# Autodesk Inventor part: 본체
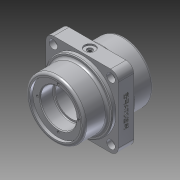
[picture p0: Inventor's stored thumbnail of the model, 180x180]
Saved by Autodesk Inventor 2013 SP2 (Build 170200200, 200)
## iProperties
Created: 2023-10
Part Number: 본체
Material: 알루미늄 6061
Document SubType Name: Modeling
Designer: i
Density: 2.71 g/cm^3
Mass: 1123.72 g
Surface Area: 610.083 cm^2
Volume: 414.656 cm^3
Author: i
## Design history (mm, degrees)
sketch "스케치1"
  geometry: L1 (-47, 47)-(47, 47); L2 (47, 47)-(47, -47); L3 (47, -47)-(-47, -47); L4 (-47, -47)-(-47, 47); L5 (-47, 47)-(47, -47); L6 (47, 47)-(-47, -47); 1 further point
  constraints: 12 end point, 2 midpoint, 2 parallel, 1 horizontal, 1 perpendicular
  dimensions: "d0" = 94 distance of L2.end L3.end; "d1" = 94 distance of L1.end L2.end
extrude "돌출1" new body sketch "스케치1" stored distance "d2" = 20; taper "d3" = 0 deg
sketch "스케치2"
  geometry: C1 r 44 at (0, 0); 1 further point
  constraints: 1 centre point, 1 coincident
  dimensions: "d4" = 88 diameter of C1
extrude "돌출2" join sketch "스케치2" distance "d6" = 5; taper "d7" = 0 deg
sketch "스케치3"
  geometry: C1 r 44 at (0, 0) reference; C2 r 38 at (0, 0)
  constraints: 1 centre point, 1 coincident
  dimensions: "d8" = 76 diameter of C2
extrude "돌출3" join sketch "스케치3" distance "d9" = 30; taper "d10" = 0 deg
sketch "스케치4"
  geometry: L1 (38, 45)-(-38, 45) reference; L2 (38, -45)-(-38, -45) reference; L3 (0, 45)-(0, -45); L4 (33, 45)-(33, 41); L5 (33, 41)-(23.5, 41); L6 (23.5, 41)-(23.5, 24); L7 (23.5, 24)-(20.5, 24); L8 (20.5, 24)-(20.5, -24); L9 (20.5, -24)-(23.5, -24); L10 (23.5, -24)-(23.5, -41); L11 (23.5, -41)-(33, -41); L12 (33, -41)-(33, -45); 1 further point
  constraints: 20 end point, 7 parallel, 3 collinear, 2 midpoint, 2 perpendicular, 2 point on line
  dimensions: "d11" = 66 diameter of L4 L3; "d13" = 4 distance of L4.start L4.end; "d14" = 47 diameter of L6 L3; "d15" = 17 distance of L5.end L6.end; "d16" = 17 distance of L9.end L10.end; "d17" = 41 diameter of L8 L3
revolve "회전1" sketch "스케치4" stored, may be unused: angle "d18" = 90 deg
fillet "모깎기1" dims "d19" = 10
sketch "스케치11" dims "d63" = 106
  geometry: L1 (0, 0)-(47, 47); L2 (0, 0)-(66.468, 0); C1 r 44 at (0, 0) reference; 1 further point
  constraints: 4 end point, 1 coincident, 1 equal length, 1 horizontal, 1 point on line, 3 other
  dimensions: "d64" = 45 deg angle of L2 L1; "d65" = 47 horizontal distance of L1.start L1.end
hole "구멍6" sketch "스케치11" at (37.477, 37.477) diameter "d66" = 6.6; stored, may be unused: countersink angle "d70" = 90 deg, drill point angle "d72" = 118 deg; dims "d67" = 8, "d68" = 11, "d69" = 7, "d71" = 10
sketch "스케치7"
  geometry: 2 further points
  constraints: 1 coincident
hole "구멍3" sketch "스케치7" at (37, 10) diameter "d34" = 5.188; stored, may be unused: countersink angle "d38" = 90 deg, drill point angle "d40" = 118 deg; dims "d35" = 16, "d36" = 7, "d37" = 4, "d39" = 8
sketch "스케치8"
  geometry: C1 r 3.5 at (37, 10) reference; 1 further point
  constraints: 1 coincident
hole "구멍4" sketch "스케치8" at (37, 10) diameter "d41" = 14; stored, may be unused: countersink angle "d45" = 90 deg, drill point angle "d47" = 0 deg; dims "d42" = 16, "d43" = 7, "d44" = 4, "d46" = 2
sketch "스케치9"
  geometry: L1 (-20, 0)-(-20, 74) reference; 2 further points
  constraints: 1 coincident, 1 other
  dimensions: "d48" = 10 distance from line of point (-10, 37) L1
feature "엠보싱1" sketch "스케치9" dims "d0" = 94, "d1" = 94, "d49" = 0.5, "d50" = 0
sketch "스케치10"
  geometry: C1 r 33 at (0, 0) reference; 1 further point
  constraints: 1 vertical alignment
  dimensions: "d51" = 27 distance of C1.centre point (0, 27)
hole "구멍5" sketch "스케치10" at (0, 27) diameter "d52" = 3.242; stored, may be unused: countersink angle "d56" = 90 deg, drill point angle "d58" = 118 deg; dims "d53" = 8, "d54" = 7, "d55" = 4, "d57" = 10
chamfer "모따기1" distance "d83" = 1; stored, may be unused: second distance "d84" = 2, angle "d85" = 45 deg
fillet "모깎기2" dims "d89" = 1
fillet "모깎기3" dims "d90" = 3
chamfer "모따기3" distance "d91" = 1; stored, may be unused: second distance "d92" = 2, angle "d93" = 45 deg
sketch "스케치13"
  geometry: C1 r 3.3 at (-37.477, 37.477) reference; C2 r 44 at (0, 0) reference; C3 r 53 at (0, 0); 1 further point
  constraints: 2 coincident, 1 centre point
  dimensions: "d94" = 106 diameter of C3
hole "구멍8" sketch "스케치13" at (-37.477, 37.477) diameter "d95" = 6.6; stored, may be unused: countersink angle "d99" = 90 deg, drill point angle "d101" = 118 deg; dims "d96" = 8, "d97" = 11, "d98" = 7, "d100" = 10
node "솔리드1"
mirror "대칭1"
pattern_circular "원형 패턴2" dims angle "d81" = 360 deg
pattern_circular "원형 패턴1" dims angle "d60" = 360 deg
mirror "대칭2"
pattern_circular "원형 패턴3" dims angle "d103" = 360 deg
